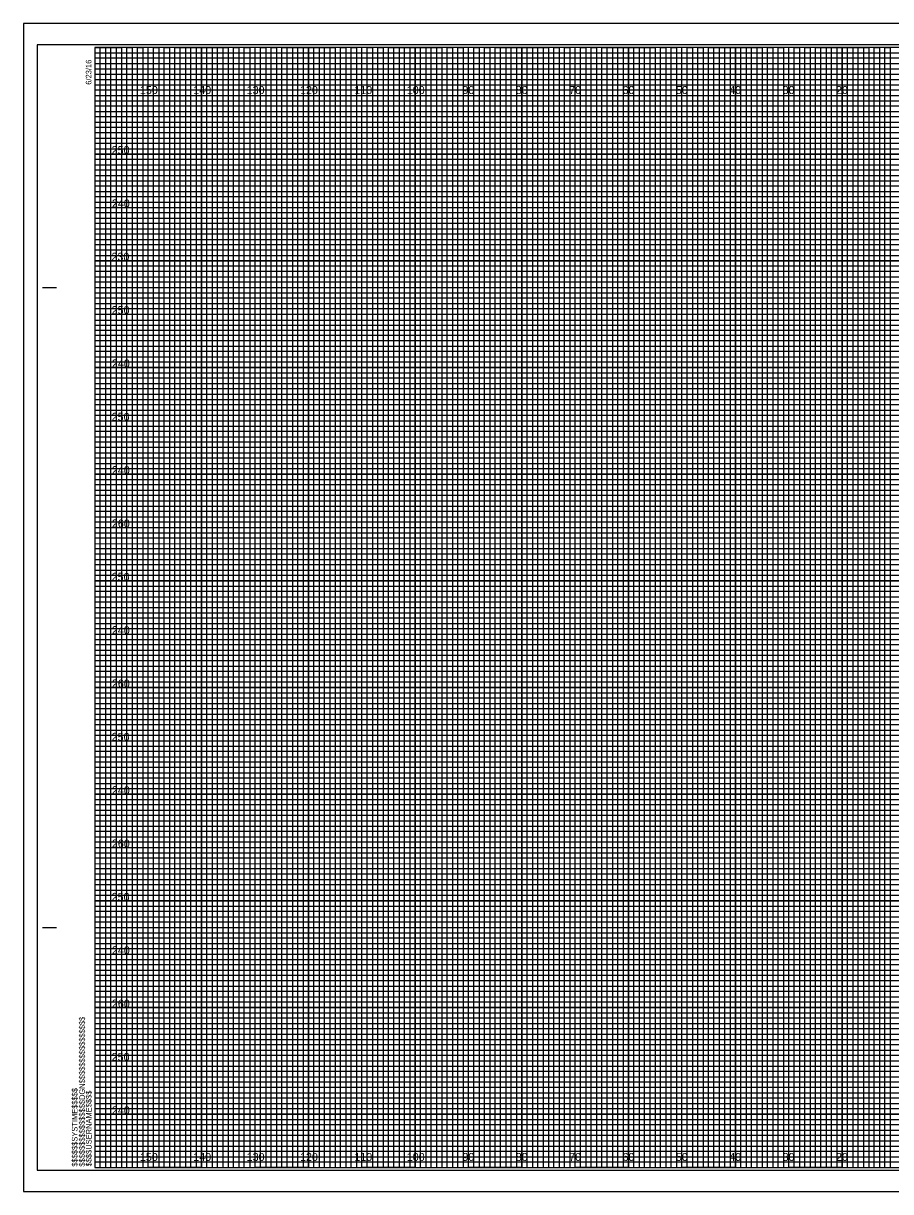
# Model space of a CAD drawing. Extents: x -13 to 359, y -5 to 2854.
# Drawn here: x -13.4 to 149.1, y 2635.5 to 2854.5 of the extents above; entities that cross this region are included whole.
import ezdxf

# ---------------------------------------------------------------- set-up
doc = ezdxf.new("R2010")
doc.units = 0
for name, color, linetype in [('Exist Cross Section Cell', 7, 'Continuous'), ('Exist XS Ground Line', 7, 'Continuous'), ('Prop CMT Concrete Structures', 7, 'Continuous'), ('Prop CMT DNC', 7, 'Continuous'), ('Prop CMT Pvmt Course 1', 7, 'Continuous'), ('Prop CMT Pvmt Course 1 CG', 7, 'Continuous'), ('Prop CMT Pvmt Course 2', 7, 'Continuous'), ('Prop CMT Shear Line', 7, 'Continuous'), ('Prop CMT Slope Grass', 7, 'Continuous'), ('Prop CMT Subgrade Earthwork', 7, 'Continuous'), ('Scratch_Level_0', 7, 'Continuous')]:
    doc.layers.add(name, color=color, linetype=linetype)

msp = doc.modelspace()

# ---------------------------------------------------------------- linework, layer by layer
at = {"layer": 'Exist XS Ground Line'}
for p, q in [((10, 2850), (0, 2850)), ((10, 2640), (10, 2850)), ((30, 2850), (20, 2850)), ((20, 2850), (20, 2640)), ((30, 2640), (30, 2850)), ((50, 2850), (40, 2850)), ((40, 2850), (40, 2640)), ((50, 2640), (50, 2850)), ((70, 2850), (60, 2850)), ((60, 2850), (60, 2640)), ((70, 2640), (70, 2850)), ((90, 2850), (80, 2850)), ((80, 2850), (80, 2640)), ((90, 2640), (90, 2850)), ((110, 2850), (100, 2850)), ((100, 2850), (100, 2640)), ((110, 2640), (110, 2850)), ((130, 2850), (120, 2850)), ((120, 2850), (120, 2640)), ((130, 2640), (130, 2850)), ((150, 2850), (140, 2850)), ((140, 2850), (140, 2640)), ((20, 2640), (10, 2640)), ((40, 2640), (30, 2640)), ((60, 2640), (50, 2640)), ((80, 2640), (70, 2640)), ((100, 2640), (90, 2640)), ((120, 2640), (110, 2640)), ((140, 2640), (130, 2640))]:
    msp.add_line(p, q, dxfattribs=at)
for points in [[(0, 2840), (320, 2840), (320, 2830), (0, 2830)], [(0, 2820), (320, 2820), (320, 2810), (0, 2810)], [(0, 2800), (320, 2800), (320, 2790), (0, 2790)], [(0, 2780), (320, 2780), (320, 2770), (0, 2770)], [(0, 2760), (320, 2760), (320, 2750), (0, 2750)], [(0, 2740), (320, 2740), (320, 2730), (0, 2730)], [(0, 2720), (320, 2720), (320, 2710), (0, 2710)], [(0, 2700), (320, 2700), (320, 2690), (0, 2690)], [(0, 2680), (320, 2680), (320, 2670), (0, 2670)], [(0, 2660), (320, 2660), (320, 2650), (0, 2650)]]:
    msp.add_lwpolyline(points, dxfattribs=at)
at = {"layer": 'Prop CMT Concrete Structures'}
for p, q in [((-9.8, 2805), (-7.3, 2805)), ((-9.7, 2805), (-7.2, 2805)), ((-9.8, 2685), (-7.3, 2685)), ((-9.7, 2685), (-7.2, 2685)), ((0, 2640), (0, 2640)), ((0, 2640), (0, 2640)), ((0, 2640), (0, 2640)), ((0, 2640), (0, 2640)), ((0, 2640), (0, 2640)), ((0, 2640), (0, 2640)), ((0, 2640), (0, 2640))]:
    msp.add_line(p, q, dxfattribs=at)
msp.add_lwpolyline([(320, 2850), (0, 2850), (0, 2640), (320, 2640)], close=True, dxfattribs=at)
at = {"layer": 'Prop CMT DNC'}
for p, q in [((323.3, 2854.5), (-13.4, 2854.5)), ((-13.4, 2854.5), (-13.4, 2635.5)), ((-13.4, 2635.5), (323.3, 2635.5))]:
    msp.add_line(p, q, dxfattribs=at)
at = {"layer": 'Prop CMT Pvmt Course 1'}
for p, q in [((0, 2849), (260, 2849)), ((260, 2847.98), (0, 2847.98)), ((0, 2847.98), (0, 2847)), ((0, 2847), (260, 2847)), ((260, 2845.89), (0, 2845.89)), ((0, 2845.89), (0, 2844)), ((0, 2844), (320, 2844))]:
    msp.add_line(p, q, dxfattribs=at)
for points in [[(0, 2843), (270, 2843), (320, 2843), (320, 2842), (0, 2842)], [(0, 2841), (320, 2841), (320, 2839), (0, 2839)], [(0, 2838), (320, 2838), (320, 2837), (0, 2836.98)], [(0, 2836), (320, 2836), (320, 2834), (0, 2834)], [(0, 2833), (320, 2833), (320, 2832), (0, 2832)], [(0, 2831), (320, 2831), (320, 2829), (0, 2829)], [(0, 2828), (320, 2828), (320, 2827), (0, 2827)], [(0, 2826), (320, 2826), (320, 2824), (0, 2824)], [(0, 2823), (320, 2823), (320, 2822), (0, 2822)], [(0, 2821), (320, 2821), (320, 2819), (0, 2819)], [(0, 2818), (320, 2818), (320, 2817), (0, 2817)], [(0, 2816), (320, 2816), (320, 2813.95), (320, 2813), (320, 2812), (0, 2812)], [(0, 2814), (320, 2814), (320, 2813), (0, 2813)], [(0, 2811), (320, 2811), (320, 2809), (0, 2809.03)], [(0, 2809.03), (320, 2809), (320, 2808), (0, 2808)], [(0, 2807), (320, 2807), (320, 2806), (0, 2806)], [(0, 2804), (320, 2804), (320, 2803), (0, 2803)], [(0, 2802), (320, 2802), (320, 2801), (0, 2801)], [(-0.07, 2798.89), (320, 2798.89), (320, 2797.88), (-0.07, 2797.88)], [(0, 2797), (320, 2797), (320, 2796), (0, 2796)], [(0, 2794), (320, 2794), (320, 2793), (0, 2793)], [(0, 2792), (320, 2792), (320, 2791), (0, 2791)], [(0, 2789), (320, 2789), (320, 2788), (0, 2788)], [(0, 2787), (320, 2787), (320, 2786), (0, 2786)], [(0, 2784), (320, 2784), (320, 2783), (0, 2783)], [(0, 2782), (320, 2782), (320, 2781), (0, 2781)], [(0, 2779), (320, 2779), (319.99, 2777.98), (0, 2778)], [(0, 2777), (320, 2777), (320, 2776), (0, 2776)], [(0, 2774), (320, 2774), (320, 2773), (0, 2773)], [(0, 2772), (320, 2772), (320, 2771), (0, 2771)], [(0, 2769), (320, 2769), (320, 2768), (0, 2768)], [(0, 2767), (320, 2767), (320, 2766), (0, 2766)], [(0, 2764), (320, 2764), (320, 2763), (0, 2763)], [(0, 2762), (320, 2762), (320, 2761), (0, 2761)], [(0, 2759), (320, 2759), (320, 2758), (0, 2758)], [(0, 2756.99), (320.07, 2756.91), (320, 2756), (0, 2756)], [(0, 2754), (320, 2754), (320, 2753), (0, 2753)], [(0, 2752), (320, 2752), (320, 2751), (0, 2751)], [(0, 2749), (320, 2749), (320, 2748), (0, 2748)], [(0, 2747), (320, 2747), (320, 2746), (0, 2746)], [(0, 2744), (320, 2744), (320, 2743), (0, 2743)], [(0, 2742), (320, 2742), (320, 2741), (0, 2741)], [(0, 2739), (320, 2739), (320, 2738), (0, 2738)], [(0, 2737), (320, 2737), (320, 2736), (0, 2736)], [(0, 2734), (320, 2734), (320, 2733), (0, 2733)], [(0, 2732), (320, 2732), (320, 2731), (0, 2731)], [(0, 2729), (320, 2729), (320, 2728), (0, 2728)], [(0, 2727), (320, 2727), (320, 2726), (0, 2726)], [(0, 2724), (320, 2724), (320, 2723), (0, 2723)], [(0, 2722), (320, 2722), (320, 2721), (0, 2721)], [(0, 2719), (320, 2719), (319.99, 2717.98), (0, 2718)], [(0, 2717), (320, 2717), (320, 2716), (0, 2716)], [(0, 2714), (320, 2714), (320, 2713), (0, 2713)], [(0, 2712), (320, 2712), (320, 2711), (0, 2711)], [(0, 2709), (320, 2709), (320, 2708), (0, 2708)], [(0, 2707), (320, 2707), (320, 2706), (0, 2706)], [(0, 2704), (320, 2704), (320, 2703), (0, 2703)], [(0, 2702), (320, 2702), (320, 2701), (0, 2701)], [(0, 2699), (320, 2699), (320, 2698), (0, 2698)], [(0, 2696.99), (320.07, 2696.91), (320, 2696), (0, 2696)], [(0, 2694), (320, 2694), (320, 2693), (0, 2693)], [(0, 2692), (320, 2692), (320, 2691), (0, 2691)], [(0, 2689), (320, 2689), (320, 2688), (0, 2688)], [(0, 2687), (320, 2687), (320, 2686), (0, 2686)], [(0, 2684), (320, 2684), (320, 2683), (0, 2683)], [(0, 2682), (320, 2682), (320, 2681), (0, 2681)], [(0, 2679), (320, 2679), (320, 2678), (0, 2678)], [(0, 2677), (320, 2677), (320, 2676), (0, 2676)], [(0, 2674), (320, 2674), (320, 2673), (0, 2673)], [(0, 2672), (320, 2672), (320, 2671), (0, 2671)], [(0, 2669), (320, 2669), (320, 2668), (0, 2668)], [(0, 2667), (320, 2667), (320, 2666), (0, 2666)], [(0, 2664), (320, 2664), (320, 2663), (0, 2663)], [(0, 2662), (320, 2662), (320, 2661), (0, 2661)], [(0, 2659), (320, 2659), (320, 2658), (0, 2658)], [(0, 2657), (320, 2657), (320, 2656), (0, 2656)], [(0, 2654), (320, 2654), (320, 2653), (0, 2653)], [(0, 2652), (320, 2652), (320, 2651), (0, 2651)], [(0, 2649), (320, 2649), (320, 2648), (0, 2648)], [(0, 2647), (320, 2647), (320, 2646), (0, 2646)], [(0, 2644), (320, 2644), (320, 2643), (0, 2643)], [(0, 2642), (320, 2642), (320, 2641), (0, 2641)]]:
    msp.add_lwpolyline(points, dxfattribs=at)
at = {"layer": 'Prop CMT Pvmt Course 1 CG'}
for points in [[(0, 2640), (1, 2640), (1, 2850), (2, 2850), (2, 2640)], [(2, 2640), (3, 2640), (3, 2850), (4, 2850), (4, 2640)], [(5, 2640), (6, 2640), (6, 2850), (7, 2850), (7, 2640)], [(7, 2640), (8, 2640), (8, 2850), (9, 2850), (9, 2640)], [(10, 2640), (11, 2640), (11, 2850), (12, 2850), (12, 2640)], [(12, 2640), (13, 2640), (13, 2850), (14, 2850), (14, 2640)], [(15, 2640), (16, 2640), (16, 2850), (17, 2850), (17, 2640)], [(17, 2640), (18, 2640), (18, 2850), (19, 2850), (19, 2640)], [(20, 2640), (21, 2640), (21, 2850), (22, 2850), (22, 2640)], [(22, 2640), (23, 2640), (23, 2850), (24, 2850), (24, 2640)], [(25, 2640), (26, 2640), (26, 2850), (27, 2850), (27, 2640)], [(27, 2640), (28, 2640), (28, 2850), (29, 2850), (29, 2640)], [(30, 2640), (31, 2640), (31, 2850), (32, 2850), (32, 2640)], [(32, 2640), (33, 2640), (33, 2850), (34, 2850), (34, 2640)], [(35, 2640), (36, 2640), (36, 2850), (37, 2850), (37, 2640)], [(37, 2640), (38, 2640), (38, 2850), (39, 2850), (39, 2640)], [(40, 2640), (41, 2640), (41, 2850), (42, 2850), (42, 2640)], [(42, 2640), (43, 2640), (43, 2850), (44, 2850), (44, 2640)], [(45, 2640), (46, 2640), (46, 2850), (47, 2850), (47, 2640)], [(47, 2640), (48, 2640), (48, 2850), (49, 2850), (49, 2640)], [(50, 2640), (51, 2640), (51, 2850), (52, 2850), (52, 2640)], [(52, 2640), (53, 2640), (53, 2850), (54, 2850), (54, 2640)], [(55, 2640), (56, 2640), (56, 2850), (57, 2850), (57, 2640)], [(57, 2640), (58, 2640), (58, 2850), (59, 2850), (59, 2640)], [(60, 2640), (61, 2640), (61, 2850), (62, 2850), (62, 2640)], [(62, 2640), (63, 2640), (63, 2850), (64, 2850), (64, 2640)], [(65, 2640), (66, 2640), (66, 2850), (67, 2850), (67, 2640)], [(67, 2640), (68, 2640), (68, 2850), (69, 2850), (69, 2640)], [(70, 2640), (71, 2640), (71, 2850), (72, 2850), (72, 2640)], [(72, 2640), (73, 2640), (73, 2850), (74, 2850), (74, 2640)], [(75, 2640), (76, 2640), (76, 2850), (77, 2850), (77, 2640)], [(77, 2640), (78, 2640), (78, 2850), (79, 2850), (79, 2640)], [(80, 2640), (81, 2640), (81, 2850), (82, 2850), (82, 2640)], [(82, 2640), (83, 2640), (83, 2850), (84, 2850), (84, 2640)], [(85, 2640), (86, 2640), (86, 2850), (87, 2850), (87, 2640)], [(87, 2640), (88, 2640), (88, 2850), (89, 2850), (89, 2640)], [(90, 2640), (91, 2640), (91, 2850), (92, 2850), (92, 2640)], [(92, 2640), (93, 2640), (93, 2850), (94, 2850), (94, 2640)], [(95, 2640), (96, 2640), (96, 2850), (97, 2850), (97, 2640)], [(97, 2640), (98, 2640), (98, 2850), (99, 2850), (99, 2640)], [(100, 2640), (101, 2640), (101, 2850), (102, 2850), (102, 2640)], [(102, 2640), (103, 2640), (103, 2850), (104, 2850), (104, 2640)], [(105, 2640), (106, 2640), (106, 2850), (107, 2850), (107, 2640)], [(107, 2640), (108, 2640), (108, 2850), (109, 2850), (109, 2640)], [(110, 2640), (111, 2640), (111, 2850), (112, 2850), (112, 2640)], [(112, 2640), (113, 2640), (113, 2850), (114, 2850), (114, 2640)], [(115, 2640), (116, 2640), (116, 2850), (117, 2850), (117, 2640)], [(117, 2640), (118, 2640), (118, 2850), (119, 2850), (119, 2640)], [(120, 2640), (121, 2640), (121, 2850), (122, 2850), (122, 2640)], [(122, 2640), (123, 2640), (123, 2850), (124, 2850), (124, 2640)], [(125, 2640), (126, 2640), (126, 2850), (127, 2850), (127, 2640)], [(127, 2640), (128, 2640), (128, 2850), (129, 2850), (129, 2640)], [(130, 2640), (131, 2640), (131, 2850), (132, 2850), (132, 2640)], [(132, 2640), (133, 2640), (133, 2850), (134, 2850), (134, 2640)], [(135, 2640), (136, 2640), (136, 2850), (137, 2850), (137, 2640)], [(137, 2640), (138, 2640), (138, 2850), (139, 2850), (139, 2640)], [(140, 2640), (141, 2640), (141, 2850), (142, 2850), (142, 2640)], [(142, 2640), (143, 2640), (143, 2850), (144, 2850), (144, 2640)], [(145, 2640), (146, 2640), (146, 2850), (147, 2850), (147, 2640)], [(147, 2640), (148, 2640), (148, 2850), (149, 2850), (149, 2640)]]:
    msp.add_lwpolyline(points, dxfattribs=at)
at = {"layer": 'Prop CMT Shear Line'}
for p, q in [((10, 2640), (10, 2850)), ((20, 2640), (20, 2850)), ((30, 2640), (30, 2850)), ((40, 2640), (40, 2850)), ((50, 2640), (50, 2850)), ((60, 2640), (60, 2850)), ((70, 2640), (70, 2850)), ((80, 2640), (80, 2850)), ((90, 2640), (90, 2850)), ((100, 2640), (100, 2850)), ((110, 2640), (110, 2850)), ((120, 2640), (120, 2850)), ((130, 2640), (130, 2850)), ((140, 2640), (140, 2850)), ((0, 2840), (320, 2840)), ((0, 2830), (320, 2830)), ((0, 2820), (320, 2820)), ((0, 2810), (320, 2810)), ((0, 2800), (320, 2800)), ((0, 2790), (320, 2790)), ((0, 2780), (320, 2780)), ((0, 2770), (320, 2770)), ((0, 2760), (320, 2760)), ((0, 2750), (320, 2750)), ((0, 2740), (320, 2740)), ((0, 2730), (320, 2730)), ((0, 2720), (320, 2720)), ((0, 2710), (320, 2710)), ((0, 2700), (320, 2700)), ((0, 2690), (320, 2690)), ((0, 2680), (320, 2680)), ((0, 2670), (320, 2670)), ((0, 2660), (320, 2660)), ((0, 2650), (320, 2650))]:
    msp.add_line(p, q, dxfattribs=at)
at = {"layer": 'Prop CMT Slope Grass'}
msp.add_lwpolyline([(-10.8, 2639.5), (322.4, 2639.5), (322.4, 2850.5), (-10.8, 2850.5)], close=True, dxfattribs=at)
at = {"layer": 'Prop CMT Subgrade Earthwork'}
msp.add_lwpolyline([(-13.4, 2635.5), (323.3, 2635.5), (323.3, 2854.5), (-13.4, 2854.5)], close=True, dxfattribs=at)
at = {"layer": 'Scratch_Level_0'}
for points in [[(0, 2850), (5, 2850), (5, 2640), (15, 2640), (15, 2850), (25, 2850), (25, 2640), (35, 2640), (35, 2850), (45, 2850), (45, 2640), (55, 2640), (55, 2850), (65, 2850), (65, 2640), (75, 2640), (75, 2850), (85, 2850), (85, 2640), (95, 2640), (95, 2850), (105, 2850), (105, 2640), (115, 2640), (115, 2850), (125, 2850), (125, 2640), (135, 2640), (135, 2850), (145, 2850), (145, 2640), (155, 2640)], [(0, 2845), (275, 2845)], [(0, 2825), (320, 2825), (320, 2835), (0, 2835)], [(0, 2805), (320, 2805), (320, 2815), (0, 2815)], [(0, 2785), (320, 2785), (320, 2795), (0, 2795)], [(0, 2765), (320, 2765), (320, 2775), (0, 2775)], [(0, 2745), (320, 2745), (320, 2755), (0, 2755)], [(0, 2725), (320, 2725), (320, 2735), (0, 2735)], [(0, 2705), (320, 2705), (320, 2715), (0, 2715)], [(0, 2685), (320, 2685), (320, 2695), (0, 2695)], [(0, 2665), (320, 2665), (320, 2675), (0, 2675)], [(0, 2645), (320, 2645), (320, 2655), (0, 2655)]]:
    msp.add_lwpolyline(points, dxfattribs=at)

# ---------------------------------------------------------------- texts
at = {"layer": 'Exist Cross Section Cell'}
for s, p in [('150', (8.44, 2841.25)), ('140', (18.44, 2841.25)), ('130', (28.44, 2841.25)), ('120', (38.44, 2841.25)), ('110', (48.62, 2841.25)), ('100', (58.44, 2841.25)), ('90', (68.86, 2841.25)), ('80', (78.86, 2841.25)), ('70', (88.86, 2841.25)), ('60', (98.86, 2841.25)), ('50', (108.86, 2841.25)), ('40', (118.86, 2841.25)), ('30', (128.86, 2841.25)), ('20', (138.86, 2841.25)), ('150', (8.44, 2641.25)), ('140', (18.44, 2641.25)), ('130', (28.44, 2641.25)), ('120', (38.44, 2641.25)), ('110', (48.62, 2641.25)), ('100', (58.44, 2641.25)), ('90', (68.86, 2641.25)), ('80', (78.86, 2641.25)), ('70', (88.86, 2641.25)), ('60', (98.86, 2641.25)), ('50', (108.86, 2641.25)), ('40', (118.86, 2641.25)), ('30', (128.86, 2641.25)), ('20', (138.86, 2641.25))]:
    msp.add_text(s, height=1.5, dxfattribs=at).set_placement(p)
at = {"layer": 'Prop CMT Concrete Structures'}
for s, p in [('6/23/16', (-0.65, 2843)), ('$$$$$$$$$$$$$$$$DGN$$$$$$$$$$$$$$$$', (-1.88, 2640.18)), ('$$$$$$SYSTIME$$$$$', (-3.26, 2640.18)), ('$$$$USERNAME$$$$', (-0.62, 2640.23))]:
    msp.add_text(s, height=1.05, rotation=90, dxfattribs=at).set_placement(p)
at = {"layer": 'Prop CMT Pvmt Course 2'}
for s, p in [('250', (3.15, 2830)), ('240', (3.19, 2820)), ('230', (3.11, 2810)), ('250', (3.15, 2800)), ('240', (3.19, 2790)), ('250', (3.15, 2780)), ('240', (3.19, 2770)), ('260', (3.19, 2760)), ('250', (3.15, 2750)), ('240', (3.19, 2740)), ('260', (3.19, 2730)), ('250', (3.15, 2720)), ('240', (3.19, 2710)), ('260', (3.19, 2700)), ('250', (3.15, 2690)), ('240', (3.19, 2680)), ('260', (3.19, 2670)), ('250', (3.15, 2660)), ('240', (3.19, 2650))]:
    msp.add_text(s, height=1.5, dxfattribs=at).set_placement(p)

doc.saveas('drawing.dxf')
